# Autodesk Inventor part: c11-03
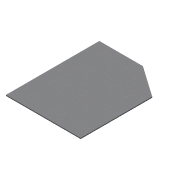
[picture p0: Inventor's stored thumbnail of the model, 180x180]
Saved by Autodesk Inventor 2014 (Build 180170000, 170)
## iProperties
Created: 2011-01
Part Number: c11-03
Material: Aluminum 6061
Document SubType Name: Sheet Metal
Designer: Thom Tremblay
Density: 2.71 g/cm^3
Sheet Metal Rule: Aluminum 3 mm
Appearance: Galvanized
Author: Thom Tremblay
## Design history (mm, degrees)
node "Face1"
  sketch "Sketch1"
    geometry: L1 (0, 0)-(240, 0); L2 (240, 0)-(240, 300); L3 (240, 300)-(0, 300); L4 (0, 300)-(0, 0); L5 (140, 300)-(240, 229.979)
    constraints: 10 end point, 2 parallel, 2 point on line, 1 horizontal, 1 perpendicular
    dimensions: "d0" = 240 distance of L3.end L2.end; "d1" = 300 distance of L2.end L1.end; "d2" = 35 deg angle of L3 L5; "d3" = 100 distance from line of L2 L5.start
body "Solid1"
face "Plate1" dims "Thickness" = 3 (derived)
other parameters: "BendRadius" = 2 (derived), "BendReliefWidth" = 3 (= Thickness), "BendReliefDepth" = 1.5 (= 0.5 x Thickness), "CornerReliefSize" = 12 (= 4 x Thickness), "SeamGap" = 0.01, "MinimumRemnant" = 6 (= 2 x Thickness), "TransitionRadius" = 2 (= BendRadius), "JacobiRadiusSize" = 2 (= BendRadius), "GapSize" = 1.5 (= 0.5 x Thickness), "d4" = 2 (= BendRadius)
